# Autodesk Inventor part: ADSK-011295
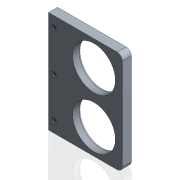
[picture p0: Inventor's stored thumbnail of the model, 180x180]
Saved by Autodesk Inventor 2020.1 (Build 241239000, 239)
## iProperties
Created: 1999-11
Part Number: ADSK-011295
Material: Pearson Aluminium
Description: PLT-05,FA,CP,03,032,045,MNT,VACUUM_CUP
Document SubType Name: Modeling
Designer: sspink
Density: 2.71 g/cm^3
Appearance: Pearson-Aluminum
Mass: 151.979 g
Surface Area: 187.771 cm^2
Volume: 56.0809 cm^3
Control State: 0
Checked Out: False
Last Check In By: sspink
Last Check In Date: 1999-12-22
Master: False
Shininess: 35.0
Length Units: 11269
Angle Units: 11279
Time Units: 11290
Mass Units: 11283
Length Display Precision: 3
Angle Display Precision: 2
Compacted: True
Dimensions: 82,5x114x10 mm
Mass: 0,152 kg
DocNumber: ADSK-011295.ipt
Folder: 01 - Themengebiete\Simplification\01 - Packaging machine\
VDS_Category: 3D Komponenten
Density: 2.71
Volumn: 52.74092718160767
Area: 185.2825979844185
PropertySet Name: Model Information
Author: sspink
Revision Number: -
Title: PLT-05,FA,CP,03,032,045,MNT,VACUUM_CUP
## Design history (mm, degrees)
node "Solide1"
  node "Extrusion1" dims "d8" = 10, "d9" = 0
  node "Extrusion2" dims "d11" = 12.7, "d12" = 0
  node "Hole1" dims "d18" = 5.5, "d19" = 10, "d20" = 5.7, "d21" = 82 deg, "d22" = 19.05, "d23" = 118 deg, "d31" = 6
  node "Fillet1" dims "d24" = 6
  node "Fillet2" dims "d25" = 3
sketch "Sketch1"
  geometry: L1 (281.989, -47.139)-(212.139, -47.139) reference; L2 (212.139, -47.139)-(212.139, -161.139) reference; L3 (212.139, -161.139)-(281.989, -161.139); L4 (281.989, -161.139)-(281.989, -47.139); L5 (250.239, -75.564)-(250.239, -132.714) reference; L6 (281.989, -104.139)-(250.239, -104.139); C1 r 23.812 at (250.239, -75.564); C2 r 23.812 at (250.239, -132.714)
  constraints: 12 end point, 2 centre point, 2 horizontal, 2 midpoint, 2 parallel, 2 vertical, 1 perpendicular
  dimensions: "d4" = 69.85 distance of L2.end L3.end; "d5" = 47.625 diameter of C1; "d6" = 47.625 diameter of C2 (= d5); "d7" = 114 distance of L3.end L1.start; "d10" = 57.15 distance of L5.start L5.end; "d26" = 31.75 distance of L6.start L6.end
sketch "Sketch3"
  geometry: L1 (-199.439, -161.139)-(-199.439, -47.139) reference; L2 (-199.439, -47.139)-(-199.439, -161.139) reference; L3 (-205.439, -59.139)-(-205.439, -149.139); 3 further points
  constraints: 2 end point, 2 midpoint, 1 coincident, 1 horizontal alignment, 1 vertical
  dimensions: "d29" = 6 distance between parallel lines of L1 L3; "d30" = 90 distance of L3.start L3.end
workplane "Work Plane1"
node "Corps solides"
node "Corps surfaciques"
sketch "Sketch2"
  geometry: L1 (10, 0)-(10, 114) reference; L2 (0, 114)-(10, 114) reference; L3 (0, 114)-(0, 0) reference; L4 (0, 0)-(10, 0) reference
other parameters: "d27" = -57.15
